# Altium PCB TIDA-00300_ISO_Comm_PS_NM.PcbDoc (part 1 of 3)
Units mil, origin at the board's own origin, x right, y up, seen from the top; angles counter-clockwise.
Board outline 2559.06 x 6299.21 mil, 4 copper layers (Top Layer, GND Layer, PWR Layer, Bottom Layer), stack 61.6 mil thick; 303 components, 144 nets, 678 pads, 244 vias.
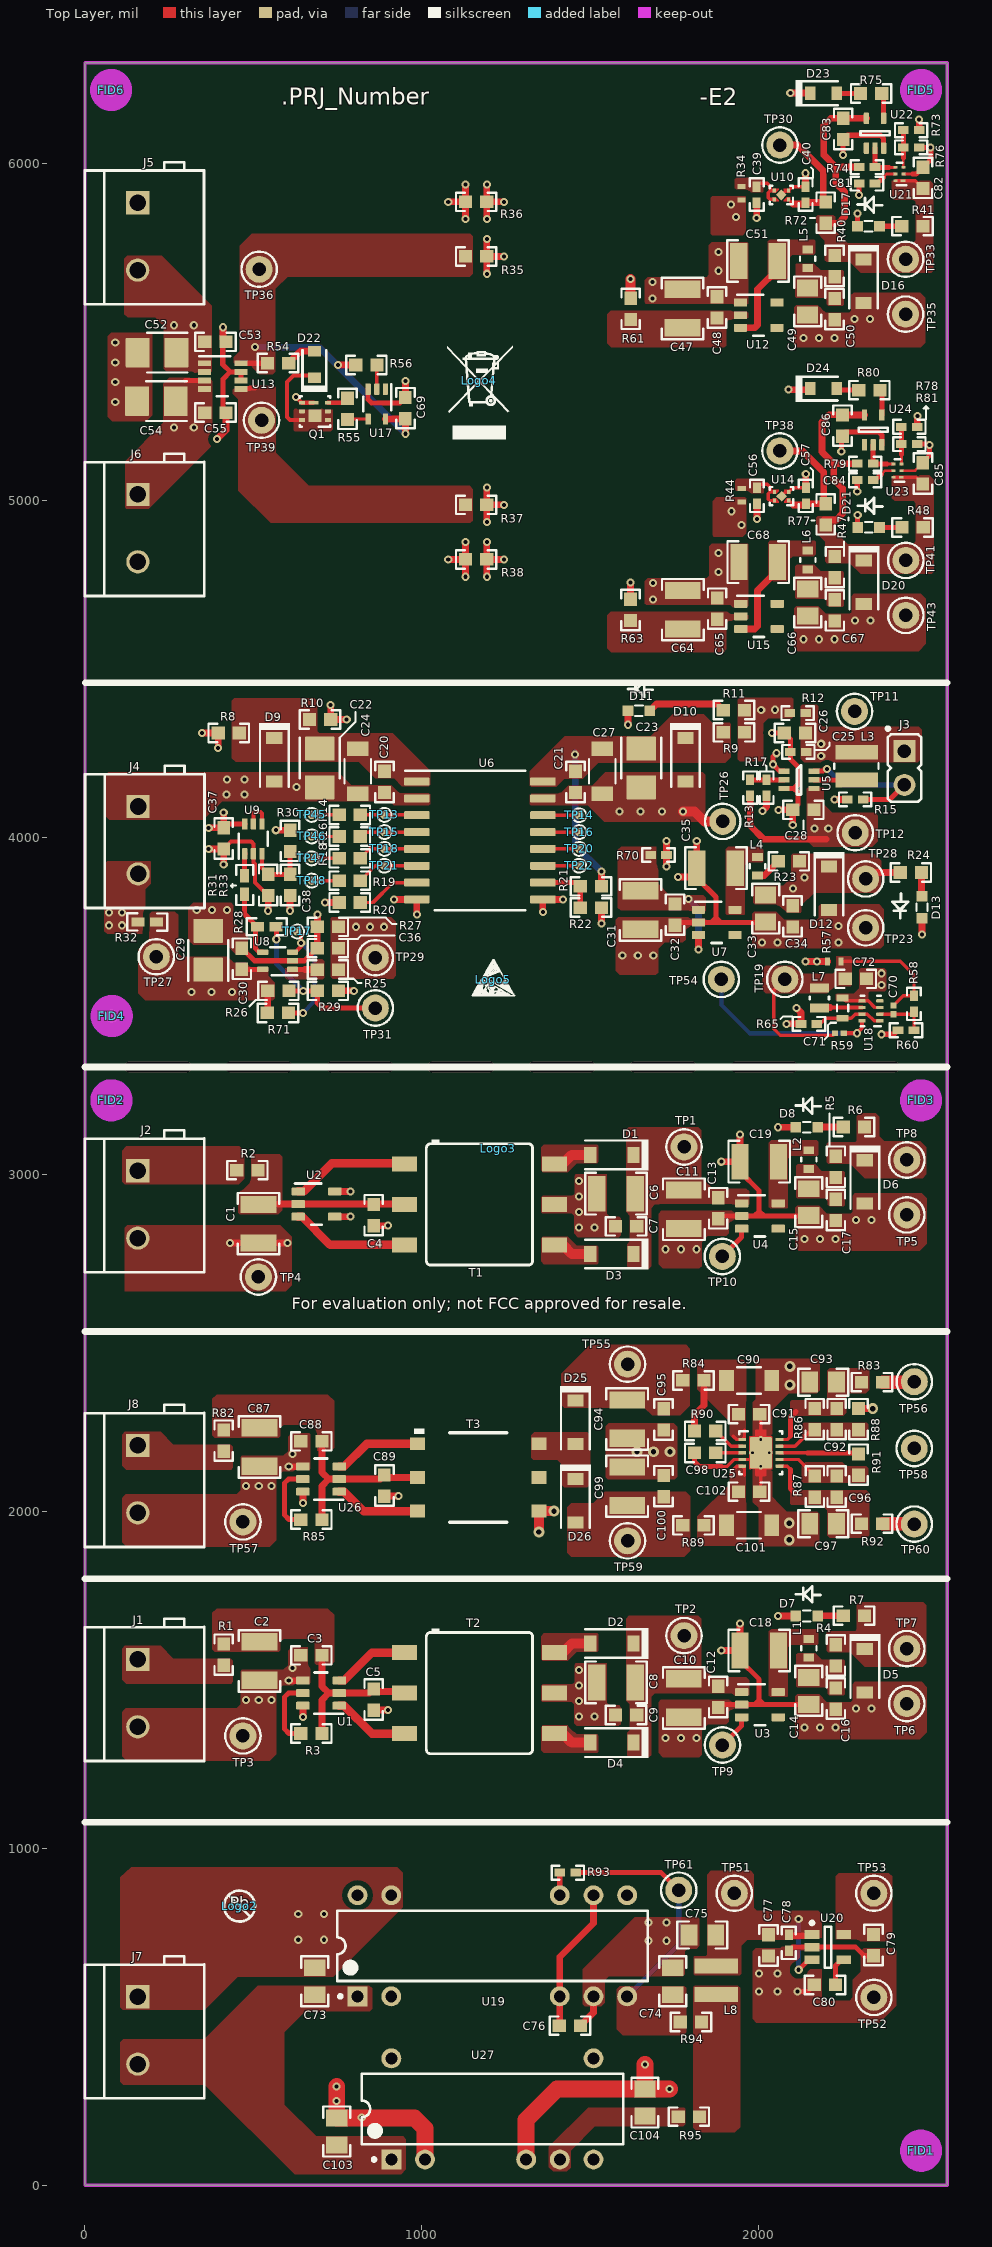
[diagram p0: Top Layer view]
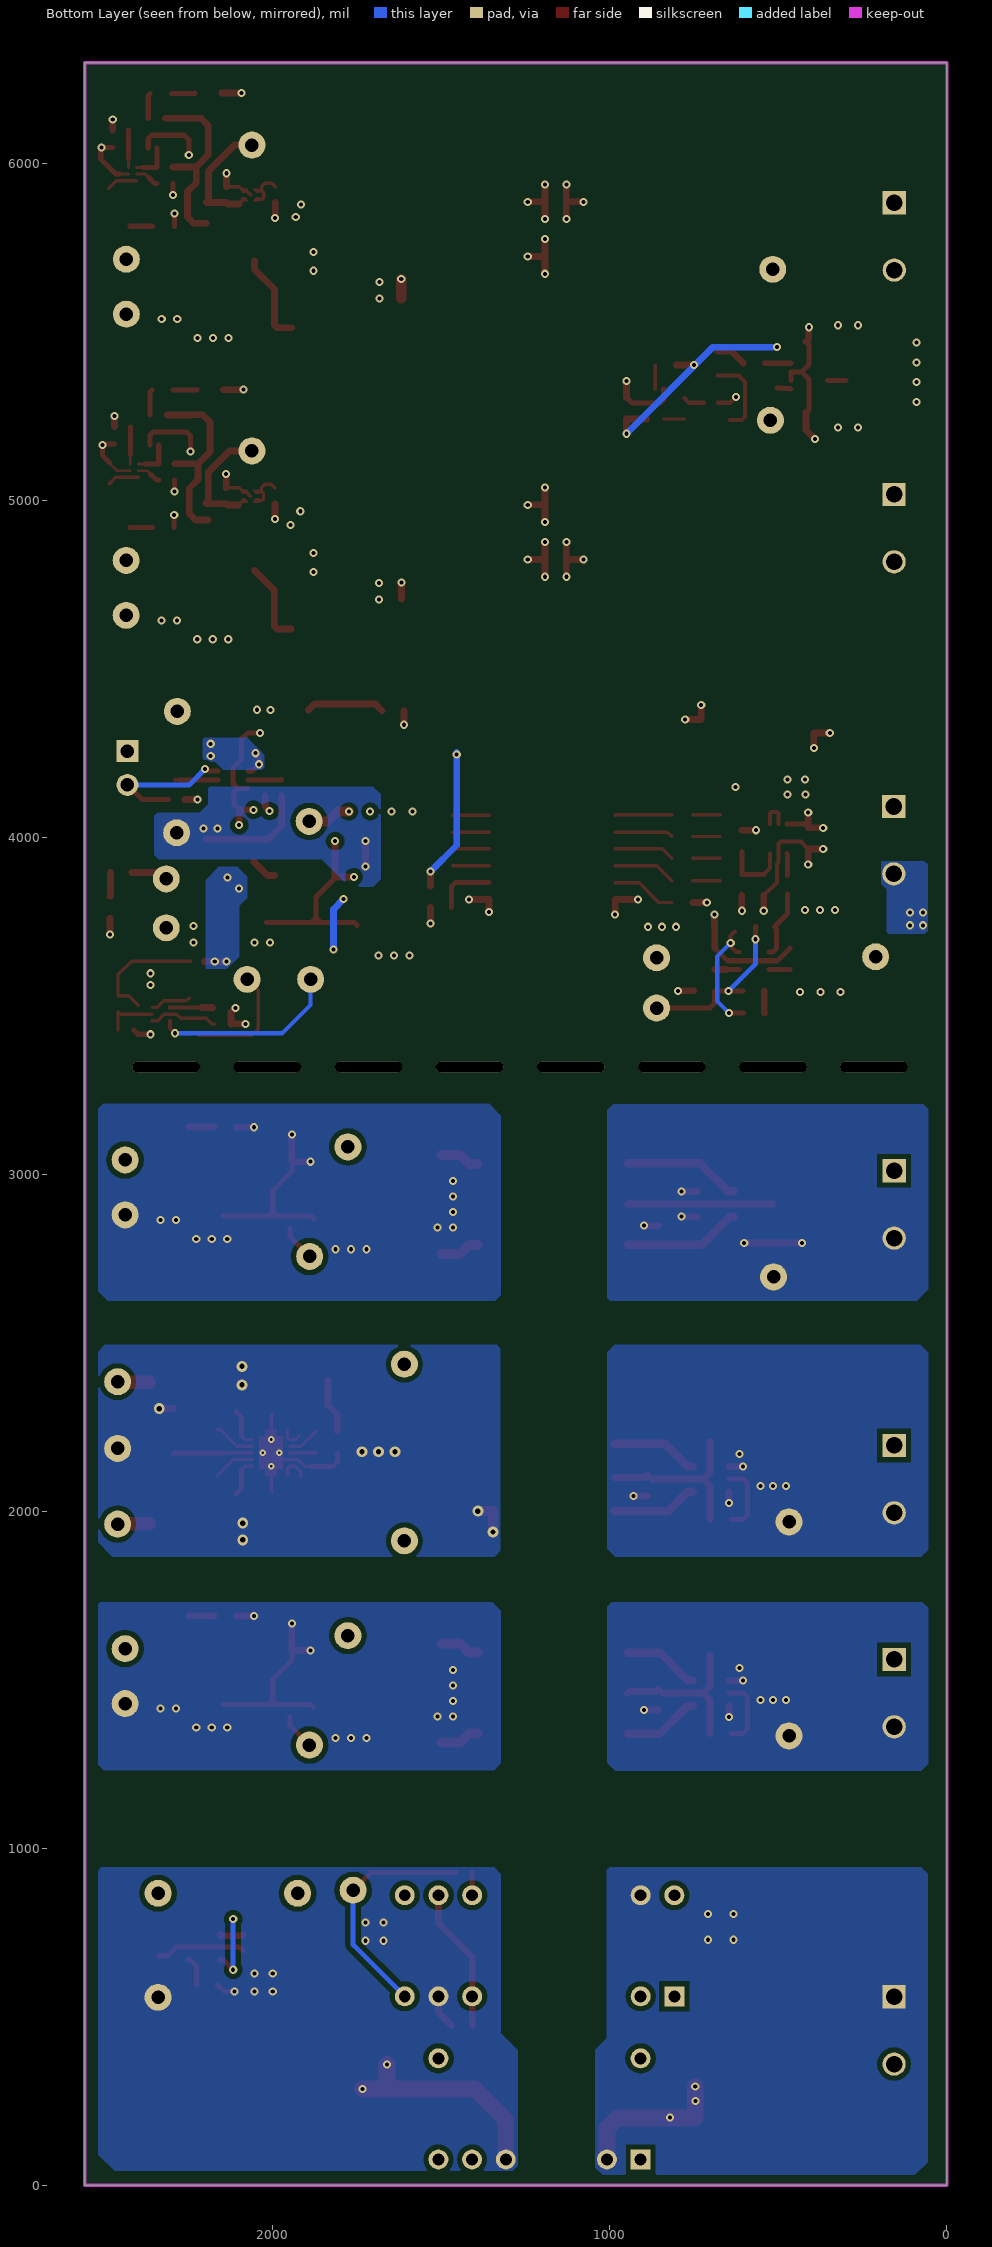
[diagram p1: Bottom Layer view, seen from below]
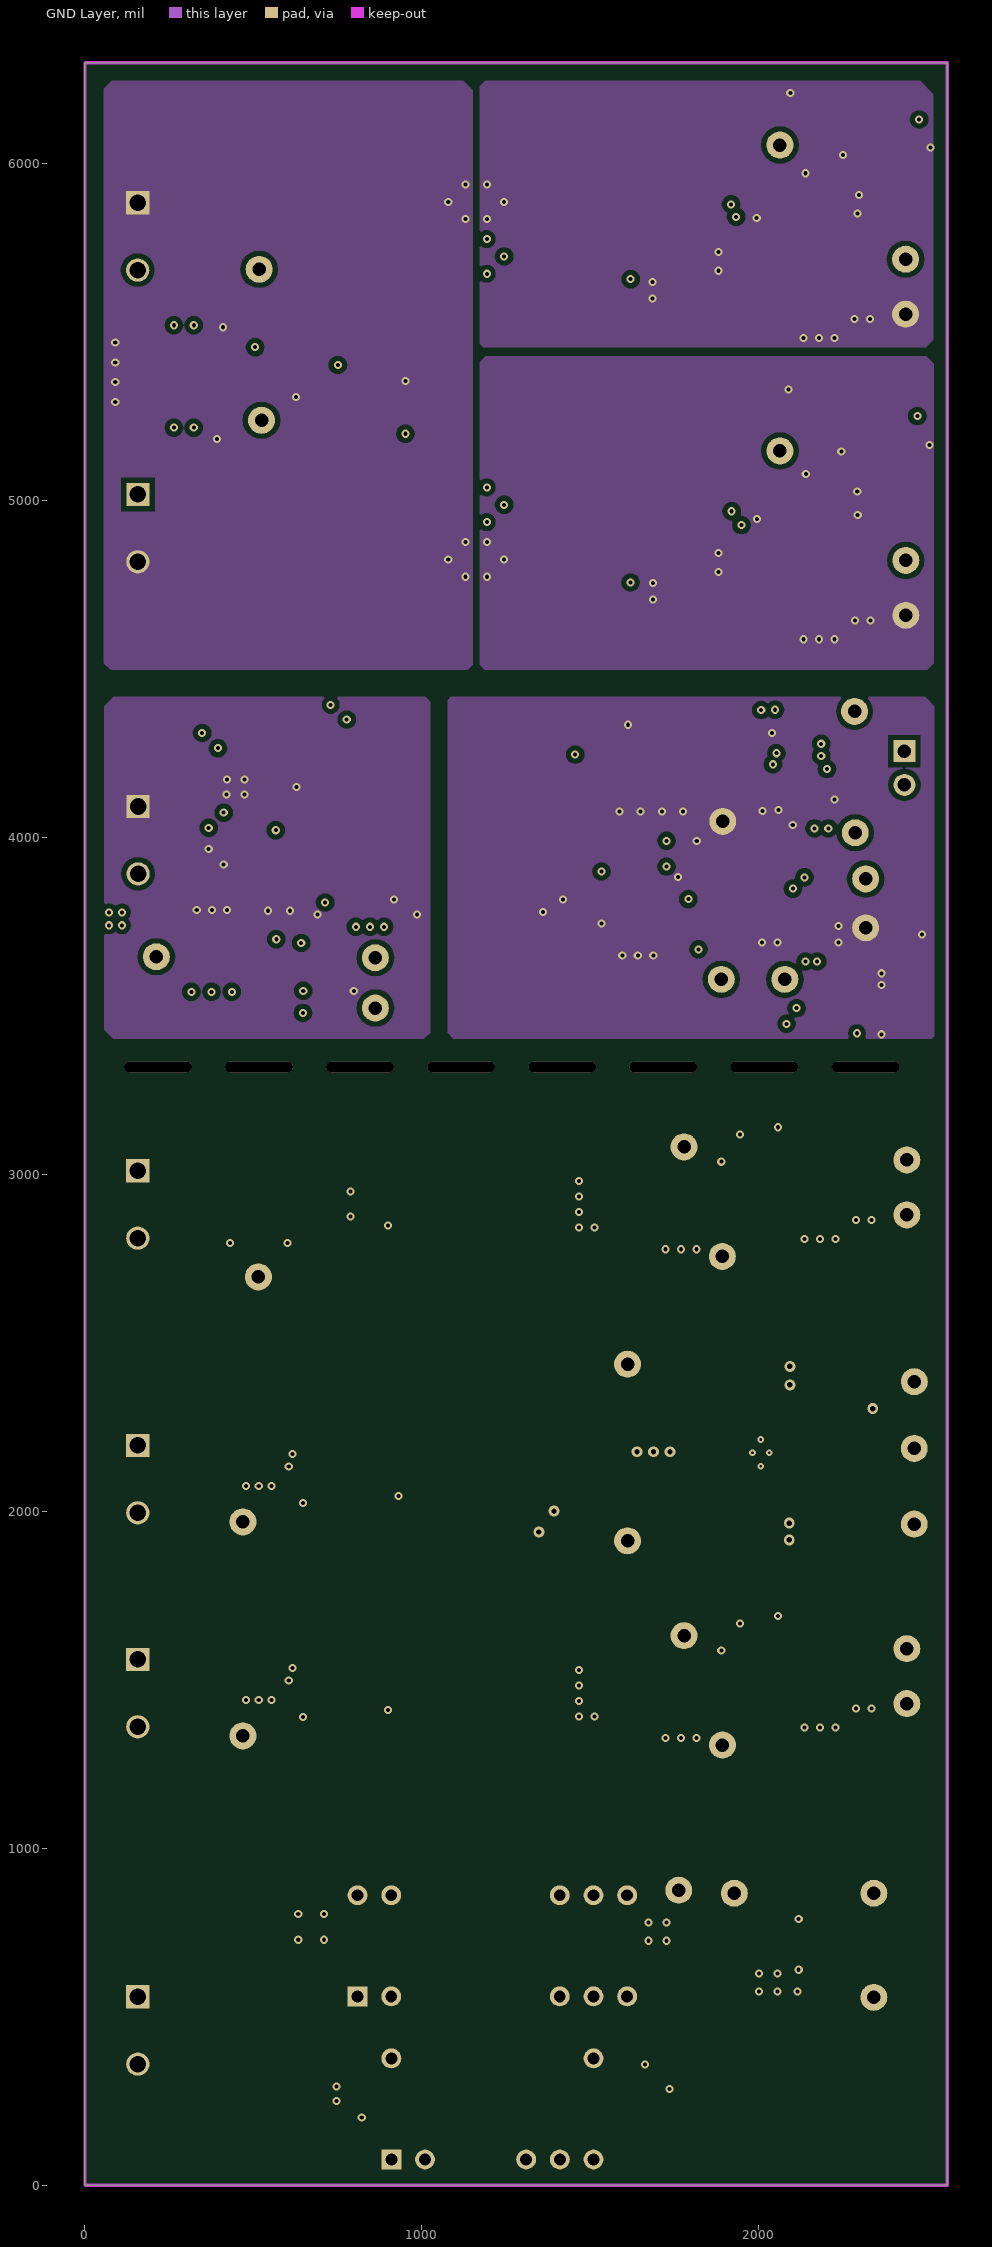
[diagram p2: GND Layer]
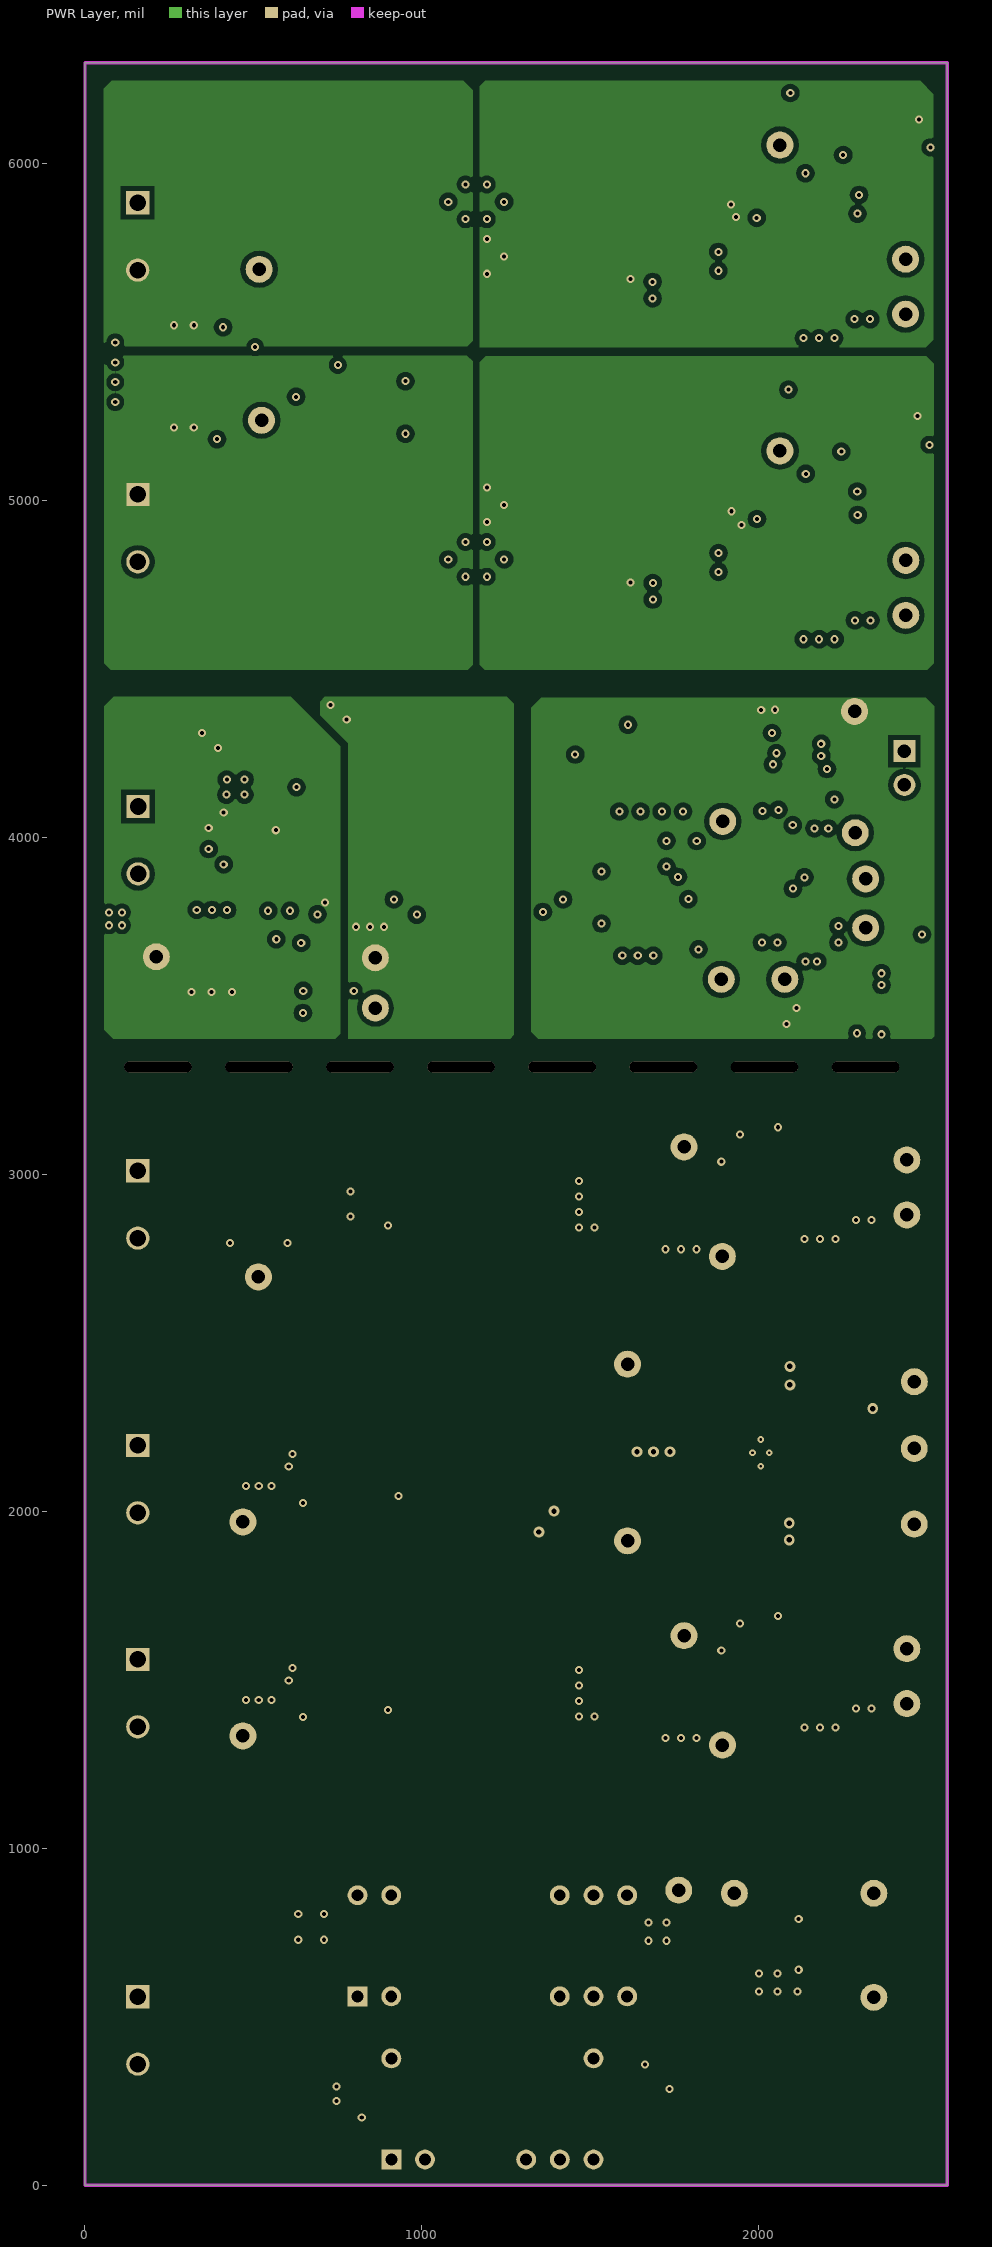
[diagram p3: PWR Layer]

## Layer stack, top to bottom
Top Solder: solder mask 0.4, Solder Resist, Dk 3.5
Top Layer: signal copper 1.4
Dielectric 1: prepreg 8, FR-4 High Tg, Dk 4.2
GND Layer: signal copper 1.4
Dielectric 2: core 40, FR-4 High Tg, Dk 4.2
PWR Layer: signal copper 1.4
Dielectric 3: prepreg 8, FR-4 High Tg, Dk 4.2
Bottom Layer: signal copper 1.4
Bottom Solder: solder mask 0.4, Solder Resist, Dk 3.5

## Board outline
0,0 2559.06,0 2559.06,6299.21 0,6299.21

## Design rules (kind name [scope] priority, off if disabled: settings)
AcuteAngle [All] p1: minimum=4.50000000000000E+0001 checktracksonly=FALSE
AssemblyTestPointUsage [All] p1: valid=2
BoardOutlineClearance BoardOutlineClearance_MountingHoles [OnCopper and InComponentClass('Mounting Holes')] p1: gap=30 ignorepadtopadclearanceinfootprint=FALSE
BoardOutlineClearance BoardOutlineClearance_Poly [OnCopper and InPoly] p2: gap=25 ignorepadtopadclearanceinfootprint=FALSE
BoardOutlineClearance [OnCopper and Not InComponentClass('Logo') and not InComponentClass('FiducialMark') and not InRegion(1000,500,4000,800)] p3: gap=15 ignorepadtopadclearanceinfootprint=FALSE
Clearance Clearance_u10 [InPadClass('U10')] p1: gap=4.5 ignorepadtopadclearanceinfootprint=FALSE
Clearance Clearance_Poly_poly [InPoly vs InPoly] p2: gap=20 ignorepadtopadclearanceinfootprint=FALSE except(0: Arc-Hole Track-Hole SMDPad-Hole THPad-Hole Via-Hole Fill-Hole Poly-Hole Region-Hole Text-Hole)
Clearance Clearance_Keepouts [((IsTrack Or IsArc) And Not InPoly) And IsFree and IsKeepOut vs ((IsTrack Or IsArc) And Not InPoly) And IsFree and IsKeepOut] p3: gap=20 ignorepadtopadclearanceinfootprint=FALSE except(0: Arc-Hole Track-Hole SMDPad-Hole THPad-Hole Via-Hole Fill-Hole Poly-Hole Region-Hole Text-Hole)
Clearance Clearance_Poly [InPolygon] p4: gap=15 ignorepadtopadclearanceinfootprint=FALSE except(0: Arc-Hole Track-Hole SMDPad-Hole THPad-Hole Via-Hole Fill-Hole Poly-Hole Region-Hole Text-Hole)
Clearance [All] p5: gap=7.87 ignorepadtopadclearanceinfootprint=FALSE except(0: Arc-SMDPad Arc-THPad Arc-Hole Track-Hole SMDPad-Hole THPad-Hole Via-Hole Fill-Hole Poly-Hole Region-Hole Text-Hole)
ComponentClearance ComponentClearance_MountingHoles_FiducialMarks [InComponentClass('Mounting Holes') vs InComponentClass('FiducialMark')] p1: gap=10 collisioncheckmode=3 verticalgap=10 showdistances=FALSE
ComponentClearance ComponentClearance_Shunt [InComponentClass('Header') vs InComponentClass('Shunt')] p2: gap=0 collisioncheckmode=3 verticalgap=0 showdistances=FALSE
ComponentClearance ComponentClearance_Logo [InComponentClass('Logo')] p3: gap=5 collisioncheckmode=3 verticalgap=5 showdistances=FALSE
ComponentClearance ComponentClearance_ScrewToNut [(HasFootprint('NY PMS 440 0025 PH')) vs (HasFootprint('Keystone_1902C'))] p4: gap=5 collisioncheckmode=3 verticalgap=10 showdistances=FALSE
ComponentClearance ComponentClearance_MountingHoles [InComponentClass('Mounting Holes')] p5: gap=250 collisioncheckmode=3 verticalgap=100000 showdistances=FALSE
ComponentClearance ComponentClearance_SmallPassives [HasFootprint('0201*') or HasFootprint('0402*') or HasFootprint('0508') or HasFootprint('0603*') or HasFootprint('0612') or HasFootprint('0805*') or HasFootprint('0815*') or HasFootprint('0830*') or HasFootprint('1206*') or HasFootprint('1210*') or HasFootprint('1808*') or HasFootprint('1812*') or HasFootprint('1825*') or HasFootprint('2010*') or HasFootprint('2220*') or HasFootprint('2225*') or HasFootprint('2512*') or HasFootprint('2728*') or HasFootprint('3518*') vs HasFootprint('0201*') or HasFootprint('0402*') or HasFootprint('0508') or HasFootprint('0603*') or HasFootprint('0612') or HasFootprint('0805*') or HasFootprint('0815*') or HasFootprint('0830*') or HasFootprint('1206*') or HasFootprint('1210*') or HasFootprint('1808*') or HasFootprint('1812*') or HasFootprint('1825*') or HasFootprint('2010*') or HasFootprint('2220*') or HasFootprint('2225*') or HasFootprint('2512*') or HasFootprint('2728*') or HasFootprint('3518*')] p6: gap=5 collisioncheckmode=3 verticalgap=5 showdistances=FALSE
ComponentClearance ComponentClearance_THtoSMT [IsThruComponent vs IsSMTComponent] p7: gap=5 collisioncheckmode=3 verticalgap=5 showdistances=FALSE
ComponentClearance ComponentClearance_THtoTH [IsThruComponent vs IsThruComponent] p8: gap=0 collisioncheckmode=3 verticalgap=10 showdistances=FALSE
ComponentClearance [All] p9: gap=1 collisioncheckmode=3 verticalgap=1 showdistances=FALSE
DiffPairsRouting [All] p1: maxlimit=100 minlimit=10 mostfreqgap=10 toplayer_minwidth=15 toplayer_maxwidth=15 toplayer_prefwidth=15 midlayer1_minwidth=15 midlayer1_maxwidth=15 midlayer1_prefwidth=15 midlayer2_minwidth=15 midlayer2_maxwidth=15 midlayer2_prefwidth=15 bottomlayer_minwidth=15 bottomlayer_maxwidth=15 bottomlayer_prefwidth=15 maxuncoupledlength=1000
FabricationTestPointUsage TestPointUsage [All] p1: valid=2 allowmultiple=FALSE
FabricationTestpoint Testpoint [All] p1: side=3 testpointundercomponent=TRUE minsize=40 maxsize=100 preferedsize=60 minholesize=0 maxholesize=40 preferedholesize=32 testpointgrid=1 allowsidetop=TRUE allowsidebottom=TRUE usegrid=TRUE gridtolerance=0.01
FanoutControl Fanout_LCC [IsLCC] p1: bgadir=Out bgaviamode=Centered fanoutstyle=Auto fanoutdirection=Alternating viagrid=1 // Fanout_LCC (Default Rule)
FanoutControl Fanout_BGA [IsBGA] p2: bgadir=Out bgaviamode=Centered fanoutstyle=Auto fanoutdirection=Alternating viagrid=1 // Fanout_BGA (Default Rule)
FanoutControl Fanout_Default [All] p4: bgadir=Out bgaviamode=Centered fanoutstyle=Auto fanoutdirection=Alternating viagrid=1 // Fanout_Default (Default Rule)
FanoutControl Fanout_Small [(CompPinCount < 5)] p5: bgadir=Out bgaviamode=Centered fanoutstyle=Auto fanoutdirection=OutThenIn viagrid=1 // Fanout_Small (Default Rule)
HoleSize [All] p1: absolutevalues=TRUE maxlimit=251 minlimit=7.87 maxpercent=80.000 minpercent=20.000
MinimumAnnularRing MinimumAnnularRing_ThermalPadVias [IsVia and InAnyComponent] p1: minimumring=4
MinimumAnnularRing [All] p2: minimumring=4
MinimumSolderMaskSliver MinimumSolderMaskSliver_Logo [InComponentClass('Logo') vs InComponentClass('Logo')] p1: minsoldermaskwidth=0.7
MinimumSolderMaskSliver [All] p2: minsoldermaskwidth=3.94
PlaneClearance [All] p1: clearance=10
PlaneConnect [All] p1: planeconnectstyle=Relief reliefexpansion=10 reliefentries=4 reliefconductorwidth=10 reliefairgap=10
PolygonConnect PolygonConnectThermalVia [isvia] p1: connectstyle=Direct reliefconductorwidth=10 reliefentries=4 polygonreliefangle="90 Angle" airgapwidth=10
PolygonConnect PolygonConnectThermalPad [((ObjectKind = 'Pad') And (((Name Like 'U*') or (Name Like 'D*')) and (InComponentClass('TIDA-00183_pg-4_Driver') or InComponentClass('TIDA-00183_pg-5_OP_Connector')))) or ((ObjectKind = 'Pad') And (Name like 'U61*'))] p2: connectstyle=Direct reliefconductorwidth=10 reliefentries=4 polygonreliefangle="90 Angle" airgapwidth=10
PolygonConnect [All] p3: connectstyle=Direct reliefconductorwidth=10 reliefentries=4 polygonreliefangle="90 Angle" airgapwidth=5
RoutingVias ThermalPadVias [IsVia and InAnyComponent] p1: holewidth=7.87 width=19.68 viastyle="Through Hole" minholewidth=7.87 minwidth=19.68 maxholewidth=12.99 maxwidth=23.62
RoutingVias [All] p2: holewidth=16 width=34 viastyle="Through Hole" minholewidth=8 minwidth=20 maxholewidth=40 maxwidth=65
SilkToBoardRegionClearance [Not ((IsComment or IsDesignator) And (Hide <> 'False')) and not InRegion(1000,500,4000,800)] p1:
SilkToSilkClearance SilkToSilkClearance_Pb-FreeLogo [(HasFootprint('Pb-Free_Overlay_Medium') OR HasFootprint('Pb-Free_Overlay_Small')) vs (HasFootprint('Pb-Free_Overlay_Medium') OR HasFootprint('Pb-Free_Overlay_Small'))] p1: silktosilkclearance=0
SilkToSilkClearance [All] p2: silktosilkclearance=4
SilkToSolderMaskClearance SilkToComponentPadClearance [IsPad and InAnycomponent] p1: minsilkscreentomaskgap=5 clearancetoexposedcopper=TRUE
SilkToSolderMaskClearance "Silk to Solder Mask Opening" [All] p2: minsilkscreentomaskgap=4 clearancetoexposedcopper=FALSE
SolderMaskExpansion [All] p1: expansion=1.97
Width [All] p1: maxlimit=100 minlimit=6 preferedwidth=10 checkconnectedcopper=TRUE
14 further rules are at their usual default settings.

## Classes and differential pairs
component class TIDA-00300_ISO_Comm_PS_NM_Pg3: C73 C74 C75 C76 C77 C78 C79 C80 C103 C104 J7 L8 R93 R94 R95 TP51 TP52 TP53 TP61 U19 U20 U27
component class FiducialMark: FID1 FID2 FID3 FID4 FID5 FID6
pad class U10: U10-1 U10-2 U10-3 U10-4 U10-5 U14-1 U14-2 U14-3 U14-4 U14-5
component class TIDA-00300_ISO_Comm_PS_NM_Pg6: C39 C40 C47 C48 C49 C50 C51 C52 C53 C54 C55 C56 C57 C64 C65 C66 C67 C68 C69 C81 C82 C83 C84 C85 C86 D16 D17 D20 D21 D22 D23 D24 J5 J6 L5 L6 Q1 R34 R35 R36 R37 R38 R40 R41 R44 R47 R48 R54 R55 R56 R61 R63 R72 R73 R74 R75 R76 R77 R78 R79 R80 R81 TP30 TP33 TP35 TP36 TP38 TP39 TP41 TP43 U10 U12 U13 U14 U15 U17 U21 U22 U23 U24
component class TIDA-00300_ISO_Comm_PS_NM_Pg5: C20 C21 C22 C23 C24 C25 C26 C27 C28 C29 C30 C31 C32 C33 C34 C35 C36 C37 C38 C70 C71 C72 D9 D10 D11 D12 D13 J3 J4 L3 L4 L7 R8 R9 R10 R11 R12 R13 R14 R15 R16 R17 R18 R19 R20 R21 R22 R23 R24 R25 R26 R27 R28 R29 R30 R31 R32 R33 R57 R58 R59 R60 R65 R70 R71 TP11 TP12 TP13 TP14 TP15 TP16 TP17 TP18 TP19 TP20 TP21 TP22 TP23 TP26 TP27 TP28 TP29 TP31 TP45 TP46 TP47 TP48 TP54 U5 U6 U7 U8 U9 U18
component class TIDA-00300_ISO_Comm_PS_NM_Pg4: C1 C2 C3 C4 C5 C6 C7 C8 C9 C10 C11 C12 C13 C14 C15 C16 C17 C18 C19 C87 C88 C89 C90 C91 C92 C93 C94 C95 C96 C97 C98 C99 C100 C101 C102 D1 D2 D3 D4 D5 D6 D7 D8 D25 D26 J1 J2 J8 L1 L2 R1 R2 R3 R4 R5 R6 R7 R82 R83 R84 R85 R86 R87 R88 R89 R90 R91 R92 T1 T2 T3 TP1 TP2 TP3 TP4 TP5 TP6 TP7 TP8 TP9 TP10 TP55 TP56 TP57 TP58 TP59 TP60 U1 U2 U3 U4 U25 U26
component class Header: J3
component class AssemblyNote: ZZ1 ZZ2 ZZ3 ZZ4
component class TIDA-00300_ISO_Comm_PS_NM_EVM_Hardware_Pg7: FID1 FID2 FID3 FID4 FID5 FID6 Logo2 Logo3 Logo4 Logo5 ZZ1 ZZ2 ZZ3 ZZ4

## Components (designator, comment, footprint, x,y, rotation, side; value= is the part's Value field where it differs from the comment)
C1 "" 1210 514.74,2853.8 r90 top value=10uF
C2 "" 1210 517.74,1555.85 r90 top value=10uF
C3 "" 0603 671.74,1572.85 r0 top value=0.1uF
C4 "" 0603 856.74,2878.94 r90 top value=0.1uF
C5 "" 0603 856.74,1441.85 r90 top value=0.1uF
C6 "" 1210 1575.74,2942.9 r180 top value=10uF
C7 "" 0603 1605.74,2845.94 r180 top value=0.1uF
C8 "" 1210 1575.74,1492.8 r180 top value=10uF
C9 "" 0603 1605.74,1395.85 r180 top value=0.1uF
C10 "" 1210 1777.02,1446.56 r90 top value=10uF
C11 "" 1210 1777.02,2896.66 r90 top value=10uF
C12 "" 0603 1879.02,1449.56 r270 top value=0.1uF
C13 "" 0603 1879.02,2899.66 r270 top value=0.1uF
C14 "" 0805_HV 2148.02,1467.56 r90 top value=4.7uF
C15 "" 0805_HV 2148.02,2917.66 r90 top value=4.7uF
C16 "" 0603 2228.02,1444.56 r270 top value=0.1uF
C17 "" 0603 2228.02,2894.66 r270 top value=0.1uF
C18 "" 1210 2001.02,1587.56 r0 top value=10uF
C19 "" 1210 2001.02,3037.66 r0 top value=10uF
C20 "C0603C104K5RACTU" 0603 888.77,4164.85 r90 top value=0.1uF
C21 "C0603C104K5RACTU" 0603 1455.77,4164.85 r90 top value=0.1uF
C22 "T491B106K016AT" 3528-21 696.77,4205.85 r270 top value=10uF
C23 "T491B106K016AT" 3528-21 1650.77,4205.85 r270 top value=10uF
C24 "GRM31CR61H106KA12L" 1206_180 809.77,4196.35 r270 top value=10uF
C25 "GRM155R71A104KA01D" 0402 2116.77,4253.85 r180 top value=0.1uF
C26 "C0603C106M9PACTU" 0603 2106.77,4309.85 r180 top value=10uF
C27 "GRM31CR61H106KA12L" 1206_180 1534.77,4196.35 r90 top value=10uF
C28 "C0603C106M9PACTU" 0603 2131.77,4081.85 r180 top value=10uF
C29 "T491B106K016AT" 3528-21 365.77,3664.99 r90 top value=10uF
C30 "" 0603 465.57,3639.99 r270 top value=0.1uF
C31 "" 1210 1648.77,3784.76 r90 top value=10uF
C32 "" 0603 1750.77,3770.76 r270 top value=0.1uF
C33 "" 0805_HV 2019.77,3788.76 r90 top value=4.7uF
C34 "" 0603 2099.77,3765.76 r270 top value=0.1uF
C35 "" 1210 1872.77,3908.76 r0 top value=10uF
C36 "" 0603 720.77,3671.49 r0 top value=0.1uF
C37 "06033C104JAT2A" 0603 411.77,3996.85 r270 top value=0.1uF
C38 "GRM1885C1H102JA01D" 0603 608.7,3858.85 r270 top value=1000pF
C39 "GRM155R61A105KE15D" 0402 1993.42,5907.47 r270 top value=1uF
C40 "GRM155R61A105KE15D" 0402 2138.42,5907.47 r90 top value=1uF
C47 "" 1210 1773.42,5569.49 r270 top value=10uF
C48 "" 0603 1875.42,5572.49 r90 top value=0.1uF
C49 "" 0805_HV 2144.42,5590.49 r90 top value=4.7uF
C50 "" 0603 2224.42,5567.49 r270 top value=0.1uF
C51 "" 1210 1997.42,5710.49 r0 top value=10uF
C52 "T491B106K016AT" 3528-21 214,5438.6 r180 top value=10uF
C53 "" 0603 387,5470.6 r180 top value=0.1uF
C54 "T491B106K016AT" 3528-21 212,5294.6 r180 top value=10uF
C55 "" 0603 387,5260.6 r180 top value=0.1uF
C56 "GRM155R61A105KE15D" 0402 1994.07,5013.79 r270 top value=1uF
C57 "GRM155R61A105KE15D" 0402 2139.07,5013.79 r90 top value=1uF
C64 "" 1210 1774.07,4675.8 r270 top value=10uF
C65 "" 0603 1876.07,4678.8 r90 top value=0.1uF
C66 "" 0805_HV 2145.07,4696.8 r90 top value=4.7uF
C67 "" 0603 2225.07,4673.8 r270 top value=0.1uF
C68 "" 1210 1998.07,4816.8 r0 top value=10uF
C69 "GMK107BJ104KAHT" 0603 951,5273.8 r90 top value=0.1uF
C70 "GRM033R71E121KA01D" 0201 2399.34,3488.38 r270 top value=120pF
C71 "C1608X7S1A475K080AC" 0603S 2248.34,3493.38 r90 top value=4.7uF
C72 "C0603C106M9PACTU" 0603 2287.34,3580.38 r0 top value=10uF
C73 "C2012X5R1H225K125AB" 0805_HV 682,606 r90 top value=2.2uF
C74 "C2012X5R1H225K125AB" 0805_HV 1744,606 r90 top value=2.2uF
C75 "C2012X5R1V226M125AC" 0805_HV 1832,743 r180 top value=22uF
C76 "UMK107AB7105KA-T" 0603 1439,474 r0 top value=1uF
C77 "C1608X5R1A106M" 0603 2028.48,712 r270 top value=10uF
C78 "GRM155R71C104JA88D" 0402 2088.64,720 r270 top value=0.1uF
C79 "C0603C225K8PACTU" 0603 2340,713 r270 top value=2.2uF
C80 "C1608C0G1E103J" 0603 2196,595 r180 top value=0.01uF
C81 "0402YC101KAT2A" 0402 2320.84,5940.06 r180 top value=100pF
C82 "" 0603 2486.84,5957.19 r90 top value=0.1uF
C83 "" 0603 2249.84,6102.48 r270 top value=0.1uF
C84 "0402YC101KAT2A" 0402 2315.37,5059.93 r180 top value=100pF
C85 "" 0603 2486.57,5080.02 r90 top value=0.1uF
C86 "" 0603 2247.99,5221.8 r270 top value=0.1uF
C87 "" 1210 517.74,2190.85 r90 top value=10uF
C88 "" 0603 671.74,2207.85 r0 top value=0.1uF
C89 "" 0603 888.64,2076.85 r90 top value=0.1uF
C90 "C1210C106M5RACTU" 1206_180 1970.58,2388.67 r180 top value=10uF
C91 "C1608X7R1E105K080AB" 0603 1970.58,2288.67 r0 top value=1uF
C92 "GMK107BJ104KAHT" 0603 2230.51,2273.67 r270 top value=0.1uF
C93 "C0805C225K8RACTU" 0805_HV 2190.58,2383.67 r180 top value=2.2uF
C94 "" 1210 1609,2273.85 r270 top value=10uF
C95 "" 0603 1717,2272.85 r270 top value=0.1uF
C96 "GMK107BJ104KAHT" 0603 2230.58,2073.67 r90 top value=0.1uF
C97 "C0805C225K8RACTU" 0805_HV 2190.58,1963.67 r180 top value=2.2uF
C98 "GRM188R70J103KA01D" 0603 1840.58,2173.67 r180 top value=0.01uF
C99 "" 1210 1609,2074.85 r270 top value=10uF
C100 "" 0603 1717,2074.85 r270 top value=0.1uF
C101 "C1210C106M5RACTU" 1206_180 1970.58,1958.67 r180 top value=10uF
C102 "C1608X7R1E105K080AB" 0603 1970.58,2058.67 r0 top value=1uF
C103 "C2012X5R1H225K125AB" 0805_HV 747,160 r90 top value=2.2uF
C104 "C2012X5R1H225K125AB" 0805_HV 1661.72,245.91 r90 top value=2.2uF
D1 "B0520LW-7-F" SOD-123 1563.74,3057.94 r180 top value=20V
D2 "B0520LW-7-F" SOD-123 1563.74,1607.85 r180 top value=20V
D3 "B0520LW-7-F" SOD-123 1563.74,2763.94 r180 top value=20V
D4 "B0520LW-7-F" SOD-123 1563.74,1313.85 r180 top value=20V
D5 "MMSZ5232B-7-F" SOD-123 2314.02,1527.56 r270 top value=5.6V
D6 "MMSZ5232B-7-F" SOD-123 2314.02,2977.66 r270 top value=5.6V
D7 "" LED0603AA 2141.74,1689.76 r0 top value=Green
D8 "" LED0603AA 2141.74,3139.86 r0 top value=Green
D9 "MMSZ5232B-7-F" SOD-123 561.77,4230.85 r270 top value=5.6V
D10 "MMSZ5232B-7-F" SOD-123 1781.77,4230.85 r270 top value=5.6V
D11 "LED_LG L29K-G2J1-24-Z" LED0603AA 1643.77,4375.85 r0 top value=Green
D12 "MMSZ5232B-7-F" SOD-123 2207.77,3848.85 r270 top value=5.6V
D13 "" LED0603AA 2483.77,3792.76 r90 top value=Green
D16 "MMSZ5232B-7-F" SOD-123 2310.42,5650.49 r270 top value=5.6V
D17 "" LED0603AA 2324.9,5813.54 r0 top value=Green
D20 "MMSZ5232B-7-F" SOD-123 2311.07,4756.8 r270 top value=5.6V
D21 "" LED0603AA 2325.56,4919.85 r0 top value=Green
D22 "LG M67K-G1J2-24-Z" LG_M67K_Green 681,5403.8 r90 top value=Green
D23 "LG M67K-G1J2-24-Z" LG_M67K_Green 2191.74,6208.48 r0 top value=Green
D24 "LG M67K-G1J2-24-Z" LG_M67K_Green 2191.74,5331.85 r0 top value=Green
D25 "B0520LW-7-F" SOD-123 1455.2,2264.85 r270 top value=20V
D26 "B0520LW-7-F" SOD-123 1455.2,2031.85 r270 top value=20V
FID1 "Fiducial" Fiducial10-30 2481,103 r0 top
FID2 "Fiducial" Fiducial10-30 78.72,3219.8 r90 top
FID3 "Fiducial" Fiducial10-30 2481,3219.8 r90 top
FID4 "Fiducial" Fiducial10-30 79.49,3469.85 r90 top
FID5 "Fiducial" Fiducial10-30 2481,6217.8 r90 top
FID6 "Fiducial" Fiducial10-30 77.72,6217.8 r90 top
J1 "ED120/2DS" CONN_ED120-2DS 156.74,1460.85 r180 top
J2 "ED120/2DS" CONN_ED120-2DS 156.74,2910.94 r180 top
J3 "PBC02SAAN" Sullins_PBC02SAAN 2431.77,4205.85 r0 top
J4 "ED120/2DS" CONN_ED120-2DS 157.77,3991.85 r180 top
J5 "ED120/2DS" CONN_ED120-2DS 156.42,5783.49 r180 top
J6 "ED120/2DS" CONN_ED120-2DS 157.07,4917.8 r180 top
J7 "ED120/2DS" CONN_ED120-2DS 157,460 r180 top
J8 "ED120/2DS" CONN_ED120-2DS 156.74,2095.85 r180 top
L1 "MMZ1608B102CTA00" MMZ1608_095 2148.02,1594 r270 top value="1000 ohm"
L2 "MMZ1608B102CTA00" MMZ1608_095 2148.02,3044.1 r270 top value="1000 ohm"
L3 "EPL3015-472MLB" EPL3015 2289.77,4211.85 r270 top value=4.7uH
L4 "MMZ1608B102CTA00" MMZ1608_095 1995.77,3914.85 r270 top value="1000 ohm"
L5 "MMZ1608B102CTA00" MMZ1608_095 2144.42,5716.93 r270 top value="1000 ohm"
L6 "MMZ1608B102CTA00" MMZ1608_095 2145.07,4823.24 r270 top value="1000 ohm"
L7 "74479275210" WE-PMCI_0805 2179.34,3523.38 r90 top value=1uH
L8 "LQH3NPN150NG0" LQH3NP_G0 1873,609 r90 top value=15uH
Logo2 "Pb-Free Symbol" Pb-Free_Overlay_Small 458.74,829 r0 top
Logo3 "FCC disclaimer" FCC_disclaimer 1226.46,3076.49 r0 top
Logo4 "WEEE logo" WEEE_Minimum 1170.14,5354.41 r0 top
Logo5 "ESD Susceptible" ESD_Overlay_small 1211,3578 r0 top
Q1 "CSD17571Q2" DQK0006C 682.61,5264.21 r180 top value=30V
R1 "CRCW06030000Z0EA" 0603 411.74,1574.85 r270 top value=0
R2 "CRCW06030000Z0EA" 0603 481.74,3012.8 r180 top value=0
R3 "CRCW06030000Z0EA" 0603 671.74,1340.85 r180 top value=0
R4 "CRCW06030000Z0EA" 0603 2228.02,1572.56 r90 top value=0
R5 "CRCW06030000Z0EA" 0603 2228.02,3022.66 r90 top value=0
R6 "RC0603FR-07820RL" 0603 2281.74,3140.86 r0 top value=820
R7 "RC0603FR-07820RL" 0603 2281.74,1690.76 r0 top value=820
R8 "CRCW06030000Z0EA" 0603 426.77,4309.85 r180 top value=0
R9 "CRCW06030000Z0EA" 0603 1925.77,4311.85 r0 top value=0
R10 "CRCW06030000Z0EA" 0603 697.77,4349.85 r0 top value=0
R11 "RC0603FR-07820RL" 0603 1925.77,4377.85 r0 top value=820
R12 "CRCW04020000Z0ED" 0402 2114.77,4368.85 r0 top value=0
R13 "CRCW04021M00FKED" 0402 1974.11,4147.61 r270 top value=1.00Meg
R14 "CRCW060349R9FKEA" 0603 785.77,4066.85 r180 top value=49.9
R15 "CRCW04021M00FKED" 0402 2285.77,4112.85 r0 top value=1.00Meg
R16 "CRCW060349R9FKEA" 0603 785.77,4002.85 r180 top value=49.9
R17 "RC0402FR-07100KL" 0402 2022.77,4147.61 r90 top value=100k
R18 "CRCW060349R9FKEA" 0603 785.77,3937.85 r180 top value=49.9
R19 "CRCW060349R9FKEA" 0603 785.77,3871.85 r180 top value=49.9
R20 "CRCW06030000Z0EA" 0603 785.77,3806.85 r180 top value=0
R21 "RC0603JR-074K7L" 0603 1501.27,3854.85 r180 top value=4.7k
R22 "CRCW06030000Z0EA" 0603 1501.27,3791.85 r180 top value=0
R23 "CRCW06030000Z0EA" 0603 2088.77,3928.85 r0 top value=0
R24 "RC0603FR-07680RL" 0603 2450.77,3895.96 r180 top value=680
R25 "CRCW06030000Z0EA" 0603 720.77,3607.85 r180 top value=0
R26 "RC0603JR-0747KL" 0603 573.77,3544.85 r180 top value=47k
R27 "RC0603FR-072K2L" 0603 720.77,3734.85 r180 top value=2.20k
R28 "RC0402JR-070RL" 0402M 539.27,3734.85 r0 top value=0
R29 "RC0603JR-0747KL" 0603 720.77,3544.85 r180 top value=47k
R30 "RC0603FR-07162KL" 0603 608.77,3989.85 r90 top value=162k
R31 "RC0402JR-070RL" 0402M 473.77,3858.85 r270 top value=0
R32 "RC0402JR-070RL" 0402M 184.77,3748.85 r0 top value=0
R33 "RC0603FR-07162KL" 0603 543.77,3858.85 r90 top value=162k
R34 "RC0402JR-070RL" 0402S 1948.42,5911.49 r90 top value=0
R35 "CRCW06030000Z0EA" 0603 1161,5724 r180 top value=0
R36 "CRCW06030000Z0EA" 0603 1161,5886 r180 top value=0
R37 "CRCW06030000Z0EA" 0603 1161,4987 r180 top value=0
R38 "CRCW06030000Z0EA" 0603 1161,4825 r180 top value=0
R40 "CRCW06030000Z0EA" 0603 2224.42,5695.49 r90 top value=0
R41 "RC0603FR-07680RL" 0603 2455.34,5813.54 r0 top value=680
R44 "RC0402JR-070RL" 0402S 1949,5015.8 r90 top value=0
R47 "CRCW06030000Z0EA" 0603 2225.07,4801.8 r90 top value=0
R48 "RC0603FR-07680RL" 0603 2456,4919.85 r0 top value=680
R54 "RC0603FR-07680RL" 0603 573,5407.6 r180 top value=680
R55 "CRCW0603300RJNEA" 0603 779,5271.8 r270 top value=300
R56 "RMCF0603ZT0R00" 0603 835,5401.8 r0 top value=0
R57 "RC0402JR-070RL" 0402S 2223.82,3631.85 r180 top value=0
R58 "CRCW0402453KFKED" 0402 2460.01,3506.41 r90 top value=453k
R59 "RC0201FR-07100KL" 0201 2238.77,3418.85 r0 top value=100k
R60 "RC0402FR-07100KL" 0402 2436.39,3427.85 r0 top value=100k
R61 "CRCW06030000Z0EA" 0603 1619.42,5568.49 r90 top value=0
R63 "CRCW06030000Z0EA" 0603 1619,4675.16 r90 top value=0
R65 "CRCW04020000Z0ED" 0402 2148.29,3446.46 r180 top value=0
R70 "CRCW04020000Z0ED" 0402 1702.1,3947.85 r180 top value=0
R71 "RC0603JR-0747KL" 0603 572.77,3479.14 r180 top value=47k
R72 "CRCW06030000Z0EA" 0603 2198,5853.85 r90 top value=0
R73 "CRCW040268K0JNED" 0402 2451.84,6098.48 r0 top value=68k
R74 "CRCW040210K0FKED" 0402 2320.84,5989.06 r0 top value=10.0k
R75 "RC0603FR-07680RL" 0603 2333,6207.48 r180 top value=680
R76 "CRCW040210K0FKED" 0402 2451.84,6047.48 r180 top value=10.0k
R77 "CRCW06030000Z0EA" 0603 2197.98,4958.85 r90 top value=0
R78 "CRCW040268K0JNED" 0402 2446.37,5218.35 r0 top value=68k
R79 "CRCW040210K0FKED" 0402 2315.37,5108.93 r0 top value=10.0k
R80 "RC0603FR-07680RL" 0603 2327.53,5327.35 r180 top value=680
R81 "CRCW040210K0FKED" 0402 2446.37,5167.35 r180 top value=10.0k
R82 "CRCW06030000Z0EA" 0603 411.74,2209.85 r270 top value=0
R83 "CRCW06030000Z0EA" 0603 2335.58,2383.67 r0 top value=0
R84 "CRCW06030000Z0EA" 0603 1805.58,2388.67 r0 top value=0
R85 "CRCW06030000Z0EA" 0603 671.74,1975.85 r180 top value=0
R86 "CRCW0603274KFKEA" 0603 2165.58,2273.67 r90 top value=274k
R87 "CRCW0603274KFKEA" 0603 2165.58,2073.67 r270 top value=274k
R88 "CRCW060331K6FKEA" 0603 2295.58,2273.67 r270 top value=31.6k
R89 "CRCW06030000Z0EA" 0603 1805.58,1958.67 r0 top value=0
R90 "CRCW06030000Z0EA" 0603 1840.58,2238.67 r0 top value=0
R91 "CRCW060327K4FKEA" 0603 2295.58,2138.67 r270 top value=27.4k
R92 "CRCW06030000Z0EA" 0603 2335.58,1963.67 r0 top value=0
R93 "CRCW040210K0FKED" 0402 1433,928 r0 top value=10.0k
R94 "CRCW06030000Z0EA" 0603 1798,485 r180 top value=0
R95 "CRCW06030000Z0EA" 0603 1792,204 r180 top value=0
T1 "750313638" Wurth_750313638 1170.74,2910.94 r0 top value=340uH
T2 "750313638" Wurth_750313638 1170.74,1460.85 r0 top value=340uH
T3 "760390014" Wurth_760390013 1167,2100.85 r0 top value=475uH
TP1 "5000" Keystone5000 1777.74,3081.55 r90 top
TP2 "5000" Keystone5000 1777.74,1631.45 r90 top
TP3 "5001" Keystone5001 468.74,1333.85 r90 top
TP4 "5001" Keystone5001 514.74,2695.8 r90 top
TP5 "5001" Keystone5001 2438.74,2879.86 r0 top
TP6 "5001" Keystone5001 2438.74,1429.76 r0 top
TP7 "5000" Keystone5000 2438.74,1592.76 r0 top
TP8 "5000" Keystone5000 2438.74,3042.86 r0 top
TP9 "5002" Keystone5002 1891.74,1306.76 r0 top
TP10 "5002" Keystone5002 1891.26,2756.48 r90 top
TP11 "5000" Keystone5000 2283.77,4373.85 r90 top
TP12 "5000" Keystone5000 2285.77,4013.85 r0 top
TP13 "TP-025-SMT" TP_25MIL-SMT 888.77,4066.85 r0 top value=STD
TP14 "TP-025-SMT" TP_25MIL-SMT 1466.77,4065.85 r0 top value=STD
TP15 "TP-025-SMT" TP_25MIL-SMT 888.77,4015.85 r0 top value=STD
TP16 "TP-025-SMT" TP_25MIL-SMT 1466.77,4015.85 r90 top value=STD
TP17 "TP-025-SMT" TP_25MIL-SMT 629.77,3720.85 r0 top value=STD
TP18 "TP-025-SMT" TP_25MIL-SMT 888.77,3965.85 r90 top value=STD
TP19 "5000" Keystone5000 2076.77,3578.85 r90 top
TP20 "TP-025-SMT" TP_25MIL-SMT 1466.77,3965.85 r90 top value=STD
TP21 "TP-025-SMT" TP_25MIL-SMT 888.77,3915.85 r0 top value=STD
TP22 "TP-025-SMT" TP_25MIL-SMT 1466.77,3915.85 r0 top value=STD
TP23 "5001" Keystone5001 2316.77,3731.76 r90 top
TP26 "5001" Keystone5001 1892.56,4047.53 r90 top
TP27 "5000" Keystone5000 211.77,3645.85 r0 top
TP28 "5000" Keystone5000 2316.77,3876.85 r0 top
TP29 "5000" Keystone5000 861.77,3642.85 r90 top
TP30 "5000" Keystone5000 2062.35,6054.49 r90 top
TP31 "5002" Keystone5002 861.77,3493.76 r90 top
TP33 "5000" Keystone5000 2435.14,5715.69 r0 top
TP35 "5001" Keystone5001 2435.14,5552.69 r0 top
TP36 "5000" Keystone5000 517.03,5685.85 r90 top
TP38 "5000" Keystone5000 2062.35,5146.85 r90 top
TP39 "5000" Keystone5000 524,5237.8 r90 top
TP41 "5000" Keystone5000 2435.79,4822 r0 top
TP43 "5001" Keystone5001 2435.79,4659 r0 top
TP45 "TP-025-SMT" TP_25MIL-SMT 672.77,4066.85 r90 top value=STD
TP46 "TP-025-SMT" TP_25MIL-SMT 672.77,4002.85 r90 top value=STD
TP47 "TP-025-SMT" TP_25MIL-SMT 672.77,3937.85 r90 top value=STD
TP48 "TP-025-SMT" TP_25MIL-SMT 672.77,3871.85 r90 top value=STD
TP51 "5000" Keystone5000 1927,867 r90 top
TP52 "5001" Keystone5001 2341,558 r90 top
TP53 "5000" Keystone5000 2341,867 r90 top
TP54 "5000" Keystone5000 1888.22,3578.85 r90 top
TP55 "5000" Keystone5000 1610,2436.85 r90 top
TP56 "5000" Keystone5000 2461,2384.85 r270 top
TP57 "5001" Keystone5001 468.74,1968.85 r90 top
TP58 "5001" Keystone5001 2460.86,2186.85 r90 top
TP59 "5000" Keystone5000 1610,1912.85 r90 top
TP60 "5000" Keystone5000 2460.86,1962.39 r90 top
TP61 "5000" Keystone5000 1762,876 r90 top
U1 "SN6505BDBVR" DBV0006A_N 700.74,1460.85 r180 top
U2 "SN6501DBVR" DBV0005A_N 687.22,2912.04 r0 top
U3 "TPS70933DBVR" DBV0005A_N 2003.02,1426.56 r0 top
U4 "TPS70950DBVR" DBV0005A_N 2003.02,2876.66 r0 top
U5 "TPS61220DCKR" DCK0006A_N 2118.77,4170.85 r0 top
U6 "ISOW7841DWER" DW0016B_N 1171.77,3990.85 r0 top
U7 "TPS76350DBVR" DBV0005A_N 1874.77,3747.76 r0 top
U8 "TPS22944DCKR" DCK0005A_N 571.77,3633.99 r180 top
U9 "TLV3012AIDCKR" DCK0006A_N 499.77,3995.85 r90 top
U10 "TLV74233PDQNR" DQN0004A 2066.42,5906.29 r180 top
U12 "TLV70450DBVR" DBV0005A_N 1999.42,5549.49 r0 top
U13 "TPS22960DCNR" DCN0008A_N 409,5368.6 r0 top
U14 "TLV74233PDQNR" DQN0004A 2067.07,5012.6 r180 top
U15 "TLV70450DBVR" DBV0005A_N 2000.07,4655.8 r0 top
U17 "SN74LVC1G14DCKR" DCK0005A_N 866,5285.8 r270 top
U18 "TPS62821DLCR" DLC0008A 2332.34,3485.38 r180 top
U19 "DCR010505P" NVE0010A 1209,711 r90 top
U20 "LP2985AIM5-3.3/NOPB" MF05A_N 2204.64,707 r0 top
U21 "TPS3897ADRYR" DRY0006A 2416.84,5968.48 r180 top
U22 "SN74LVC1G17DCKR" DCK0005A_N 2344.46,6089.48 r90 top
U23 "TPS3895ADRYR" DRY0006A 2411.37,5088.35 r180 top
U24 "SN74LVC1G17DCKR" DCK0005A_N 2338.99,5209.35 r90 top
U25 "TPS7A3901DSC" DSC0010J 2005.58,2173.87 r0 top
U26 "SN6505BDBVR" DBV0006A_N 700.74,2095.85 r180 top
U27 "DCP010505BP" NVA0007A 1209.17,227 r90 top
ZZ1 "This Assembly Note is for PCB labels only" AssemblyNoteLabel 205.19,7114.07 r0 top
ZZ2 "This Assembly Note will show in the PcbDoc and associated outputs" AssemblyNote 205.19,7005.18 r0 top
ZZ3 "This Assembly Note will show in the PcbDoc and associated outputs" AssemblyNote 205.19,6916.63 r0 top
ZZ4 "This Assembly Note will show in the PcbDoc and associated outputs" AssemblyNote 205.19,6828.07 r0 top

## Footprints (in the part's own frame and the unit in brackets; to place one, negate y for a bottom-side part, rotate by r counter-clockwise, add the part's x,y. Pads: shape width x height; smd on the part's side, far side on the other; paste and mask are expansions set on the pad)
0201 [mm] "Data from Kemet datasheet CC101_COM dated 7/28/11"
  rect 0.46x0.42 smd mask+0.048: 1(-0.33,0) 2(0.33,0)
  body extent -0.31,-0.16 0.31,0.16, height 0.26
0402 [mm] "0402 from SM-752 data"
  rect 0.8x0.6 smd: 1(-0.6,0) 2(0.6,0)
  silkscreen extent -1.22,-0.52 1.22,0.52, body extent -0.55,-0.3 0.55,0.3, height 0.6
0402M [mm] "0402 from SM-752 data"
  rect 1x0.7 smd: 1(-0.7,0) 2(0.7,0)
  silkscreen extent -1.5,-0.64 1.51,0.65, body extent -0.55,-0.3 0.55,0.3, height 0.6
0402S [mil] "Based on C0402S footprint from PADS legacy"
  rect 15x24 smd: 1(-20,0) 2(20,0)
  body extent -22,-12 22,12, height 24
0603 [mm] "0603 from SM-752 data"
  rect 1x0.95 smd: 1(-0.8,0) 2(0.8,0)
  silkscreen extent -1.52,-0.69 1.52,0.69, body extent -0.87,-0.47 0.87,0.47, height 1
0603S [mil]
  rect 20x35 smd: 1(-30,0) 2(30,0)
  silkscreen extent -10,-17 10,17, body extent -34,-19 34,19, height 39
0805_HV [mil] "0805 with 30mil clearance between pads"
  rect 50x63 smd: 1(-40,0) 2(40,0)
  silkscreen extent -74,-40 74,40, body extent -43,-29 43,29, height 57
1206_180 [mm] "1206_180"
  rect 1.1x1.6 smd: 1(-1.7,0) 2(1.7,0)
  silkscreen extent -0.9,-1 0.9,1, body extent -1.75,-0.95 1.75,0.95, height 1.8
1210 [mm] "1210 from SM-752 data"
  rect 1.3x2.7 smd: 1(-1.45,0) 2(1.45,0)
  silkscreen extent -2.32,-1.57 2.32,1.57, body extent -1.7,-1.35 1.7,1.35, height 1.35
3528-21 [mm] "Medium Density IPC, based on Kemet datasheet 2016-10-20"
  rrect6% 1.8x2.23 smd: 1(-1.46,0) 2(1.46,0)
  silkscreen extent -2.29,-1.5 0.76,1.5, body extent -1.85,-1.5 1.85,1.5, height 2.12
AssemblyNote [mil] "Assembly Note"
AssemblyNoteLabel [mil] "Assembly Note for PCB Labels"
CONN_ED120-2DS [mm] "ONSHORE"
  rect 1.75x1.75 hole 1.25: 1(0,-2.54)
  round 1.75 hole 1.25: 2(0,2.54)
  silkscreen extent -5,-5.6 4,5.12, body extent -5,-5.6 4.15,5.12, height 13.1
DBV0005A_N [mm] "SOT23, 5-Leads, Body 2.9x1.6mm, Pitch 0.95mm, Lead Span 2.8mm, IPC Medium Density"
  rrect17% 1x0.6 smd: 1(-1.375,0.95) 2(-1.375,0) 3(-1.375,-0.95) 4(1.375,-0.95) 5(1.375,0.95)
  silkscreen extent -1.63,-1.55 0.38,1.55, body extent -1.42,-1.46 1.42,1.46, height 1.09
DBV0006A_N [mm] "SOT23, 6-Leads, Body 2.9x1.6mm, Pitch 0.95mm, Lead Span 2.8mm, IPC Medium Density"
  rrect17% 1x0.6 smd: 1(-1.375,0.95) 2(-1.375,0) 3(-1.375,-0.95) 4(1.375,-0.95) 5(1.375,0) 6(1.375,0.95)
  silkscreen extent -1.68,-1.55 0.5,1.55, body extent -1.42,-1.46 1.42,1.46, height 1.12
DCK0005A_N [mm] "SOT353, 5-Leads, Body 2x1.3mm, Pitch 0.65mm, Lead Span 2.1mm, IPC Medium Density"
  rrect25% 0.85x0.4 smd: 1(-1.125,0.65) 2(-1.125,0) 3(-1.125,-0.65) 4(1.125,-0.65) 5(1.125,0.65)
  silkscreen extent -1.48,-1.02 0.55,1.1, body extent -1.14,-1 1.14,1, height 0.95
DCK0006A_N [mm] "SOT23, 6-Leads, Body 2x1.3mm, Pitch 0.65mm, Lead Span 2.1mm, IPC Medium Density"
  rrect25% 0.85x0.4 smd: 1(-1.125,0.65) 2(-1.125,0) 3(-1.125,-0.65) 4(1.125,-0.65) 5(1.125,0) 6(1.125,0.65)
  silkscreen extent -0.15,-1.1 0.15,1.1, body extent -1.14,-1 1.14,1, height 0.95
DCN0008A_N [mm] "SOP, 8-Leads, Body 2.9x1.6mm, Pitch 0.65mm, IPC Medium Density"
  rrect22% 1x0.45 smd: 1(-1.375,0.975) 2(-1.375,0.325) 3(-1.375,-0.325) 4(-1.375,-0.975) 5(1.375,-0.975) 6(1.375,-0.325) 7(1.375,0.325) 8(1.375,0.975)
  silkscreen extent -1.75,-1.5 0.58,1.5, body extent -1.41,-1.45 1.41,1.45, height 1.45
DLC0008A [mm] "VSON-HR-8"
  rrect40% 0.55x0.25 smd: 1(-0.675,0.75) 2(-0.675,0.25) 3(-0.675,-0.25) 4(-0.675,-0.75) 5(0.675,-0.75) 6(0.675,-0.25) 7(0.675,0.25) 8(0.675,0.75)
  silkscreen extent -0.75,-1.15 0.75,1.15, body extent -0.8,-1.05 0.8,1.05, height 1.02
DQK0006C [mm] "WSON"
  rrect12% 0.9x0.86 on Top Paste: 0(0,0.325)
  rrect34% 0.7x0.29 on Top Paste: 0(0.095,-0.65)
  rrect33% 0.45x0.3 smd: 1(-0.975,0.65) 2(-0.975,0) 3(-0.975,-0.65) 4(0.975,-0.65) 5(0.975,0) 6(0.975,0.65)
  rrect33% 0.75x0.3 smd paste-0.15: 7(0.095,-0.65)
  rrect11% 1x0.95 smd paste-0.5: 8(0,0.325)
  silkscreen extent -1.15,-1.15 1.15,1.15, body extent -1,-1 1,1, height 0.82
DQN0004A [mm] "SON, 0.65mm pitch"
  rect 0.25x0.31 smd paste-1 mask-0.31: 1(-0.535,0.325) 2(-0.535,-0.325) 3(0.535,-0.325) 4(0.535,0.325)
  rect 0.58x0.58 smd rot 45 paste-0.065 mask-0.05: 5(0,0)
  Top Layer region: 0.66,0.48 0.2,0.48 0.2,0.379 0.409,0.17 0.66,0.17
  Top Layer region: -0.66,-0.48 -0.2,-0.48 -0.2,-0.379 -0.409,-0.17 -0.66,-0.17
  Top Layer region: 0.66,-0.48 0.2,-0.48 0.2,-0.379 0.409,-0.17 0.66,-0.17
  Top Layer region: -0.66,0.48 -0.2,0.48 -0.2,0.379 -0.409,0.17 -0.66,0.17
  silkscreen extent -0.88,-0.7 0.88,0.7, body extent -0.52,-0.53 0.53,0.53, height 0.42
DRY0006A [mm] "PSON, 6-Leads, Body 1x1.45mm, Pitch 0.5mm, TI Recommended"
  rect 0.35x0.2 smd: 1(-0.275,0.5)
  rect 0.3x0.2 smd: 2(-0.3,0) 3(-0.3,-0.5) 4(0.3,-0.5) 5(0.3,0) 6(0.3,0.5)
  silkscreen extent -0.5,-0.85 0.2,0.85, body extent -0.53,-0.75 0.53,0.75, height 0.61
DSC0010J [mm] "SON, 10-Leads, Body 3x3mm, Pitch 0.5mm, Thermal Pad 2.4x1.65mm, TI Recommended"
  rrect40% 0.6x0.25 smd: 1(-1.4,1) 2(-1.4,0.5) 3(-1.4,0) 4(-1.4,-0.5) 5(-1.4,-1) 6(1.4,-1) 7(1.4,-0.5) 8(1.4,0) 9(1.4,0.5) 10(1.4,1)
  rrect40% 0.25x0.34 on Top Paste: 11(-0.25,-1.53) 11(-0.25,1.53) 11(0.25,-1.53) 11(0.25,1.53)
  rrect9% 1.5x1.06 on Top Paste: 11(0,-0.63) 11(0,0.63)
  rrect12% 1.65x2.4 smd paste-1 mask-2: 11(0,0)
  Top Layer region: -0.775,-1.25 -0.425,-1.25 -0.425,-1.65 -0.417,-1.688 -0.396,-1.721 -0.363,-1.742 -0.325,-1.75 -0.325,-1.75 -0.325,-1.75 -0.175,-1.75 -0.175,-1.75 -0.137,-1.742 -0.104,-1.721 -0.083,-1.688 -0.075,-1.65 -0.075,-1.65 -0.075,-1.25 0.075,-1.25 0.075,-1.65 0.083,-1.688 0.104,-1.721 0.137,-1.742 0.175,-1.75 0.175,-1.75 0.175,-1.75 0.325,-1.75 0.325,-1.75 0.363,-1.742 0.396,-1.721 0.417,-1.688 0.425,-1.65 0.425,-1.65 0.425,-1.25 0.775,-1.25 0.813,-1.242 0.846,-1.221 0.867,-1.188 0.875,-1.15 0.875,-1.15 0.875,1.15 0.867,1.188 0.846,1.221 0.813,1.242 0.775,1.25 0.775,1.25 0.425,1.25 0.425,1.65 0.417,1.688 0.396,1.721 0.363,1.742 0.325,1.75 0.325,1.75 0.175,1.75 0.137,1.742 0.104,1.721 0.083,1.688 0.075,1.65 0.075,1.65 0.075,1.25 -0.075,1.25 -0.075,1.65 -0.083,1.688 -0.104,1.721 -0.137,1.742 -0.175,1.75 -0.175,1.75 -0.325,1.75 -0.363,1.742 -0.396,1.721 -0.417,1.688 -0.425,1.65 -0.425,1.65 -0.425,1.25 -0.775,1.25 -0.813,1.242 -0.846,1.221 -0.867,1.188 -0.875,1.15 -0.875,1.15 -0.875,-1.15 -0.867,-1.188 -0.846,-1.221 -0.813,-1.242 -0.775,-1.25
  silkscreen extent -1.63,-1.63 1.63,1.63, body extent -1.5,-1.5 1.5,1.5, height 0.81
DW0016B_N [mm] "SOIC, 16-Leads, Body 10.5x7.6mm, Pitch 1.27mm, IPC Medium Density"
  rrect17% 1.9x0.6 smd: 1(-4.75,4.445) 2(-4.75,3.175) 3(-4.75,1.905) 4(-4.75,0.635) 5(-4.75,-0.635) 6(-4.75,-1.905) 7(-4.75,-3.175) 8(-4.75,-4.445) 9(4.75,-4.445) 10(4.75,-3.175) 11(4.75,-1.905) 12(4.75,-0.635) 13(4.75,0.635) 14(4.75,1.905) 15(4.75,3.175) 16(4.75,4.445)
  silkscreen extent -5.6,-5.25 3.4,5.25, body extent -5.17,-5.15 5.17,5.15, height 2.59
EPL3015 [mm] "COILCRAFT"
  rect 1.12x3.2 smd: 1(-1.04,0) 2(1.04,0)
  silkscreen extent -0.22,-1.68 0.23,1.65, body extent -1.6,-1.6 1.6,1.6, height 1.55
ESD_Overlay_small [mil]
  silkscreen extent -62,-48 64,61
FCC_disclaimer [mil]
Fiducial10-30 [mm]
  round 1 smd mask+1: 1(0,0)
  Top Layer keep-out circle w1.678: c0,0 r0.75
Keystone5000 [mil] "For Keystone 500x miniature loop terminals"
  round 80 hole 40: 1(0,0)
  silkscreen extent -52,-52 52,52, body extent -49,-49 49,49, height 182
Keystone5001 [mil] "For Keystone 500x miniature loop terminals"
  round 80 hole 40: 1(0,0)
  silkscreen extent -52,-52 52,52, body extent -49,-49 49,49, height 182
Keystone5002 [mil] "For Keystone 500x miniature loop terminals"
  round 80 hole 40: 1(0,0)
  silkscreen extent -52,-52 52,52, body extent -49,-49 49,49, height 182
LED0603AA [mil]
  rect 32x32 smd: 1(-32.48,0) 2(32.48,0)
  silkscreen extent -33,-16 41,88
LG_M67K_Green [mm] "SMD, 2-Leads, Body 2x1.4mm, Pitch 2mm"
  rect 0.8x1 smd mask+0: 1(-1,0) 2(1,0)
  silkscreen extent -2.1,-1 1.05,1, body extent -1.05,-0.75 1.05,0.75, height 1.4
LQH3NP_G0 [mm] "MURATA"
  rect 1.15x3.3 smd: 1(-1.075,0) 2(1.075,0)
  body extent -1.6,-1.6 1.6,1.6, height 1.01
MF05A_N [mm] "SOT23, 5-Leads, Body 2.9x1.6mm, Pitch 0.95mm, Lead Span 2.8mm, IPC Medium Density"
  rect 1.1x0.65 smd: 1(-1.2,0.95) 2(-1.2,0) 3(-1.2,-0.95) 4(1.2,-0.95) 5(1.2,0.95)
  silkscreen extent -1.32,-1.55 0.25,1.95, body extent -0.9,-1.55 0.9,1.55, height 1.19
MMZ1608_095 [mm] "TDK"
  rect 0.6x0.8 smd: 1(-0.7,0) 2(0.7,0)
  silkscreen extent -0.15,-0.58 0.15,0.58, body extent -0.87,-0.47 0.87,0.47, height 0.95
NVA0007A [mm] "DIP, 7-Leads, Body 19.18x6.605mm, Pitch 2.54mm"
  rect 1.5x1.5 hole 0.9: 1(-3.81,7.62)
  round 1.5 hole 0.9: 2(-3.81,5.08) 5(-3.81,-2.54) 6(-3.81,-5.08) 7(-3.81,-7.62) 8(3.81,-7.62) 14(3.81,7.62)
  silkscreen extent -3.93,-9.85 2.65,9.85, body extent -3.95,-9.85 3.95,9.85, height 5.33
NVE0010A [mm] "DIP, 10-Leads, Body 22.86x6.61mm, Pitch 2.54mm"
  rect 1.5x1.5 hole 0.9: 1(-3.81,10.16)
  round 1.5 hole 0.9: 2(-3.81,7.62) 7(-3.81,-5.08) 8(-3.81,-7.62) 9(-3.81,-10.16) 10(3.81,-10.16) 11(3.81,-7.62) 12(3.81,-5.08) 17(3.81,7.62) 18(3.81,10.16)
  silkscreen extent -3.93,-11.7 2.65,11.7, body extent -3.95,-11.68 3.95,11.68, height 5.33
Pb-Free_Overlay_Small [mil]
  silkscreen extent -46,-46 46,46
SOD-123 [mm] "On Semi recommended land pattern"
  rect 0.915x1.22 smd: 1(-1.637,0) 2(1.637,0)
  silkscreen extent -2.74,-1.17 2.03,1.17, body extent -1.93,-0.9 1.93,0.9, height 1.35
Sullins_PBC02SAAN [mm] "Sullins 100mil, 1x2, 230 mil above insulator"
  rect 1.65x1.65 hole 1.016: 1(0,1.27)
  round 1.65 hole 1.016: 2(0,-1.27)
  silkscreen extent -1.37,-2.54 1.27,3.1, body extent -1.27,-2.54 1.27,2.54, height 8.38
TP_25MIL-SMT [mil]
  round 25 smd mask-2.5: 1(0,0)
  silkscreen extent -21,-21 21,21
WE-PMCI_0805 [mm] "SMD, 2-Leads, Body 2x1.25mm"
  rect 0.7x1.45 smd: 1(-0.75,0) 2(0.75,0)
  silkscreen extent -0.1,-0.72 0.1,0.72, body extent -1,-0.62 1,0.63, height 1
WEEE_Minimum [mil] "WEEElie bin"
  silkscreen extent -95,-172 99,104
Wurth_750313638 [mm] "SMD, 6-Leads, Body 8x9.14mm, Pitch 3.05mm"
  rect 1.9x1.14 smd: 1(-5.655,3.05) 2(-5.655,0) 3(-5.655,-3.05) 4(5.655,-3.05) 5(5.655,0) 6(5.655,3.05)
  silkscreen extent -4,-4.57 4,4.88, body extent -6.35,-4.57 6.35,4.57, height 7.62
Wurth_760390013 [mil] "Wurth"
  rect 44x38 smd: 1(-180,100) 2(-180,0) 3(-180,-100) 4(180,-100) 5(180,0) 6(180,100)
  silkscreen extent -190,-132 85,145, body extent -198,-135 198,130, height 166

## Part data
C1 C2 C6 C8 C10 C11 C18 C19 C31 C35 C47 C51 C64 C68 C87 C94 C99: library part GMK325AB7106MM-T, "CAP, CERM, 10uF, 35V, +/-20%, X7R, 1210", Cap_Case=1210, Manufacturer="Taiyo Yuden", Supplier Part Number 1=587-2779-1-ND, TempCo=X7R, Tolerance_%=20, Value1=Unknown, Value2=35V, ValueDisplayed=10µF
C3 C4 C5 C7 C9 C12 C13 C16 C17 C30 C32 C34 C36 C48 C50 C53 C55 C65 C67 C82 C83 C85 C86 C88 C89 C95 C100: library part C0603C104K5RACTU, "CAP, CERM, 0.1uF, 50V, +/-10%, X7R, 0603", Cap_Case=0603, Manufacturer=Kemet, Supplier Part Number 1=399-5089-1-ND, TempCo=X7R, Tolerance_%=10, Value1=Unknown, Value2=50V, ValueDisplayed=0.1µF
C14 C15 C33 C49 C66: library part C2012X5R1H475K125AB, "4.7µF ±10% 50V X5R Ceramic Capacitor -55°C ~ 85°C", Cap_Case=0805, Manufacturer=TDK, PartNumber=GRM21BR61H475KE51L, Supplier Part Number 1=490-10751-1-ND, TempCo=X5R, Tolerance_%=10, Value1=Unknown, Value2=50V, ValueDisplayed=4.7µF
C20 C21: "CAP, CERM, 0.1uF, 50V, +/-10%, X7R, 0603", Cap_Case=0603, Manufacturer=Kemet, Supplier Part Number 1=399-5089-1-ND, TempCo=X7R, Tolerance_%=10, Value1=Unknown, Value2=50V, ValueDisplayed=0.1µF
C22 C23 C29 C52 C54: library part 293D106X9016B2TE3, "CAP, TA, 10 µF, 16 V, +/- 10%, 2 ohm, SMD", Cap_Case=B, Manufacturer=Vishay-Sprague, Supplier Part Number 1=399-3706-1-ND, Tolerance_%=10, Value1="2 ohm", Value2=16V, ValueDisplayed=10µF
C24 C27: "CAP, CERM, 10 µF, 50 V, +/- 10%, X5R, 1206", Cap_Case=1206, Manufacturer=MuRata, Supplier Part Number 1=490-5961-1-ND, TempCo=X5R, Tolerance_%=10, Value1=Unknown, Value2=50V, ValueDisplayed=10µF
C25: "CAP, CERM, 0.1uF, 10V, +/-10%, X7R, 0402", Cap_Case=0402, Manufacturer=MuRata, Supplier Part Number 1=GRM155R71A104KA01D-ND, TempCo=X7R, Tolerance_%=10, Value1=Unknown, Value2=10V, ValueDisplayed=0.1µF
C26 C28 C72: "CAP, CERM, 10 µF, 6.3 V, +/- 20%, X5R, 0603", Cap_Case=0603, Manufacturer=Kemet, Supplier Part Number 1=399-5504-1-ND, TempCo=X5R, Tolerance_%=20, Value1="0.004 ohm", Value2=6.3V, ValueDisplayed=10µF
C37: "CAP, CERM, 0.1 µF, 25 V, +/- 5%, X7R, 0603", Cap_Case=0603, Manufacturer=AVX, Supplier Part Number 1=478-3713-1-ND, TempCo=X7R, Tolerance_%=5, Value1="0.05 ohm", Value2=25V, ValueDisplayed=0.1µF
C38: "CAP, CERM, 1000 pF, 50 V, +/- 5%, C0G/NP0, 0603", Cap_Case=0603, Manufacturer=MuRata, Supplier Part Number 1=490-1451-1-ND, TempCo=C0G/NP0, Tolerance_%=5, Value1=Unknown, Value2=50V, ValueDisplayed=1000pF
C39 C40 C56 C57: library part CMP-0006563-2, "CAP, CERM, 1 uF, 10 V, +/- 10%, X5R, 0402", Cap_Case=0402, Manufacturer=MuRata, Supplier Part Number 1=490-3890-1-ND, TempCo=X5R, Tolerance_%=10%, Value1=Unknown, Value2=10V, ValueDisplayed=1uF
C69 C92 C96: library part 06033C104JAT2A, "0.1µF ±10% 35V Ceramic Capacitor X5R 0603", Cap_Case=0603, Manufacturer="Taiyo Yuden", Supplier Part Number 1=587-3357-1-ND, TempCo=X7R, Tolerance_%=5, Value1="0.05 ohm", Value2=25V, ValueDisplayed=0.1µF
C70: library part CMP-0009765-1, "CAP, CERM, 120 pF, 25 V, +/- 10%, X7R, 0201", Cap_Case=0201, Manufacturer=MuRata, Supplier Part Number 1=490-3173-1-ND, TempCo=X7R, Tolerance_%=10%, Value1=Unknown, Value2=25V, ValueDisplayed=120pF
C71: "CAP, CERM, 4.7 µF, 10 V,+/- 10%, X7S, 0603", Cap_Case=0603, Manufacturer=TDK, Supplier Part Number 1=445-14258-1-ND, TempCo=X7S, Tolerance_%=10, Value2=10V, ValueDisplayed=4.7µF
C73 C74 C103 C104: library part CMP-0007836-1, "CAP, CERM, 2.2 uF, 50 V, +/- 10%, X5R, 0805", Cap_Case=0805, Manufacturer=TDK, Supplier Part Number 1=445-5976-1-ND, TempCo=X5R, Tolerance_%=10%, Value1="0.00366 ohm", Value2=50V, ValueDisplayed=2.2uF
C75: library part CMP-0007844-1, "CAP, CERM, 22 uF, 35 V, +/- 20%, X5R, 0805", Cap_Case=0805, Manufacturer=TDK, Supplier Part Number 1=445-14428-1-ND, TempCo=X5R, Tolerance_%=20%, Value1="0.00205 ohm", Value2=35V, ValueDisplayed=22uF
C76: library part CMP-0007508-1, "CAP, CERM, 1 uF, 50 V, +/- 10%, X7R, 0603", Cap_Case=0603, Manufacturer="Taiyo Yuden", Supplier Part Number 1=587-3247-1-ND, TempCo=X7R, Tolerance_%=10%, Value1=Unknown, Value2=50V, ValueDisplayed=1uF
C77: "CAP, CERM, 10uF, 10V, +/-20%, X5R, 0603", Cap_Case=0603, Manufacturer=TDK, Supplier Part Number 1=445-6853-1-ND, TempCo=X5R, Tolerance_%=20, Value1="0.0078 ohm", Value2=10V, ValueDisplayed=10µF
C78: library part 0402YC132KAT2A, "CAP CER 0.1UF 16V 5% X7R 0402", Cap_Case=0402, Manufacturer="Murata Electronics North America", Supplier Part Number 1=0402YC132KAT2A-ND, TempCo=X7R, Tolerance_%=10
C79: "CAP, CERM, 2.2uF, 10V, +/-10%, X5R, 0603", Cap_Case=0603, Manufacturer=Kemet, Supplier Part Number 1=399-4911-1-ND, TempCo=X5R, Tolerance_%=10, Value1=Unknown, Value2=10V, ValueDisplayed=2.2µF
C80: "CAP, CERM, 0.01uF, 25V, +/-5%, C0G/NP0, 0603", Alternate Manufacturer=-, Cap_Case=0603, Manufacturer=TDK, Supplier Part Number 1=445-2664-1-ND, TempCo=C0G/NP0, Tolerance_%=5, Value1=?, Value2=25V, ValueDisplayed=0.01µF
C81 C84: "CAP, CERM, 100 pF, 16 V,+/- 10%, X7R, 0402", Cap_Case=0402, Manufacturer=AVX, Supplier Part Number 1=478-7887-1-ND, TempCo=X7R, Tolerance_%=10, Value2=16V, ValueDisplayed=100pF
C90 C101: library part CL31B106KBHNNNE, "CAP, CERM, 10µF ±20% 50V Ceramic Capacitor X7R 1210", Cap_Case=1206, Manufacturer=Kemet, Supplier Part Number 1=399-11630-1-ND, TempCo=X7R, Tolerance_%=10, Value1=Unknown, Value2=50V, ValueDisplayed=10µF
C91 C102: library part 885012206052, "CAP, CERM,  1µF ±10% 25V Ceramic Capacitor X7R 0603", Cap_Case=0603, Manufacturer=TDK, Supplier Part Number 1=445-5956-1-ND, TempCo=X7R, Tolerance_%=10, Value1=Unknown, Value2=16V, ValueDisplayed=1µF
C93 C97: "CAP, CERM, 2.2uF, 10V, +/-10%, X7R, 0805", Cap_Case=0805, Manufacturer=Kemet, Supplier Part Number 1=399-3522-1-ND, TempCo=X7R, Tolerance_%=10, Value1="0.008 ohm", Value2=10V, ValueDisplayed=2.2µF
C98: "CAP, CERM, 0.01 µF, 6.3 V, +/- 10%, X7R, 0603", Cap_Case=0603, Manufacturer=MuRata, Supplier Part Number 1=GRM188R70J103KA01D-ND, TempCo=X7R, Tolerance_%=10, Value1=Unknown, Value2=6.3V, ValueDisplayed=0.01µF
D1 D2 D3 D4 D25 D26: library part MBR0520LT1G, "Diode, Schottky, 20V, 0.5A, SOD-123", Manufacturer="Diodes Inc", Supplier Part Number 1=B0520LW-FDICT-ND, Value1=0.5A, Value2=0.385V
D5 D6 D9 D10 D12 D16 D20: "Diode, Zener, 5.6 V, 500 mW, SOD-123", Manufacturer="Diodes Inc.", Power_W=0.5, Supplier Part Number 1=MMSZ5232B-FDICT-ND, Value1=0.5W
D7 D8 D13 D17 D21: library part "LED_LG L29K-G2J1-24-Z", "LED SmartLED Green 570NM", Alternate Manufacturer=LED, Manufacturer=OSRAM, PartNumber="LG L29K-G2J1-24-Z", Supplier Part Number 1=475-2709-1-ND
D11: "LED GREEN DIFFUSED 0603 SMD", Alternate Manufacturer=LED, Manufacturer="ROHM Semiconductor", PartNumber=SML-D12M8WT86, Supplier Part Number 1=511-1578-1-ND
D22 D23 D24: "LED, Green, SMD", Color=Green, Manufacturer=OSRAM, Supplier Part Number 1=475-1406-1-ND, Value1=W, Value2=1.8V
FID1 FID2 FID3 FID4 FID5 FID6: "Fiducial mark.  There is nothing to buy or mount.", Manufacturer=N/A
J1 J2 J4 J5 J6 J7 J8: "TERMINAL BLOCK 5.08MM VERT 2POS, TH", Manufacturer="On-Shore Technology", Supplier Part Number 1=ED1609-ND
J3: "Header, 100mil, 2x1, Gold, TH", Manufacturer="Sullins Connector Solutions", Supplier Part Number 1=S1011E-02-ND
L1 L2 L4 L5 L6: "Ferrite Bead, 1000 ohm @ 100 MHz, 0.3 A, 0603", Manufacturer=TDK, Supplier Part Number 1=445-8672-1-ND, Value1="0.6 ohm", Value2=0.3A
L3: "Inductor, Shielded, Ferrite, 4.7 µH, 1.2 A, 0.14 ohm, SMD", Manufacturer=Coilcraft, Supplier Part Number 1=994-EPL3015-472MLB, Value1="0.14 ohm", Value2=1.2A, ValueDisplayed=4.7µH
L7: library part CMP-0064308-1, "Inductor, Shielded, 1 uH, 1.8 A, 0.078 ohm, SMD", Manufacturer="Wurth Elektronik", Supplier Part Number 1=732-9707-1-ND, Value1="0.078 ohm", Value2=1.8A, ValueDisplayed=1uH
